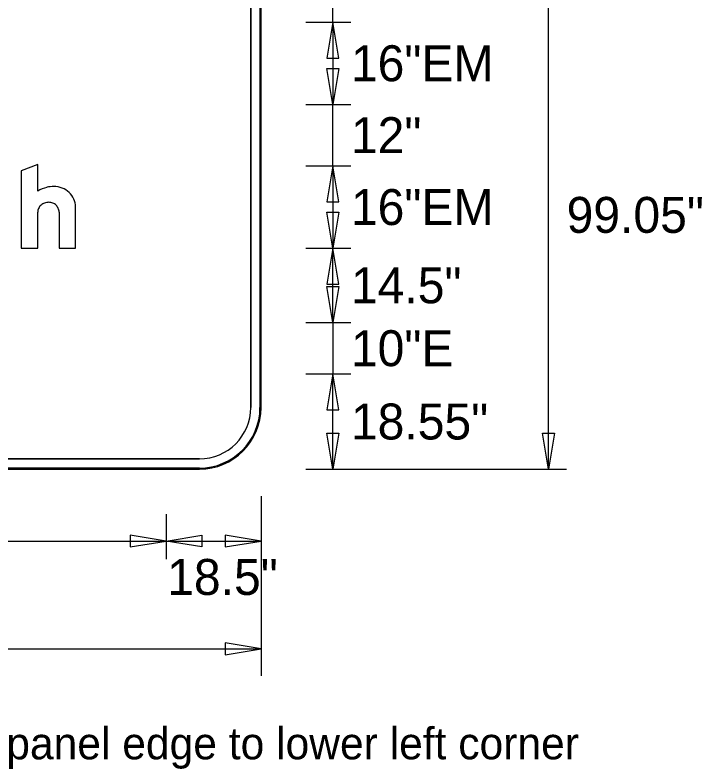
# Model space of a CAD drawing. Extents: x 2149961 to 2150220, y 145114 to 145240.
# Drawn here: x 2150101.79 to 2150112.93, y 145141.43 to 145153.67 of the extents above; entities that cross this region are included whole.
import ezdxf

# ---------------------------------------------------------------- set-up
doc = ezdxf.new("R2010")
doc.units = 0
for name, color, linetype in [('GSBWFILL', 7, 'Continuous'), ('GSCOLORFILL', 7, 'Continuous'), ('GSDIMS', 7, 'Continuous'), ('GSOUTLINE', 7, 'Continuous'), ('Level 1', 7, 'Continuous')]:
    doc.layers.add(name, color=color, linetype=linetype)

msp = doc.modelspace()

# ---------------------------------------------------------------- linework, layer by layer
at = {"layer": 'GSBWFILL'}
for p, q in [((2150105.612, 145159.8), (2150105.612, 145147.3)), ((2150105.779, 145147.3), (2150105.779, 145159.8)), ((2150104.779, 145146.466), (2150091.28, 145146.466)), ((2150091.28, 145146.3), (2150104.779, 145146.3))]:
    msp.add_line(p, q, dxfattribs=at)
for points in [[(2150102.155, 145150.812), (2150102.155, 145151.244), (2150101.888, 145151.141), (2150101.888, 145149.887), (2150102.155, 145149.887), (2150102.155, 145150.472)], [(2150102.501, 145150.472), (2150102.501, 145149.887), (2150102.768, 145149.887), (2150102.768, 145150.56)]]:
    msp.add_lwpolyline(points, dxfattribs=at)
for centre, radius, start, end in [((2150102.413, 145150.407), 0.48, 103.4695, 122.4943), ((2150102.417, 145150.354), 0.533, 90, 102.6043), ((2150102.417, 145150.512), 0.375, 68.8636, 90), ((2150102.426, 145150.535), 0.35, 46.975, 68.8636), ((2150102.44, 145150.55), 0.33, 23.9317, 46.975), ((2150102.462, 145150.56), 0.306, 0, 23.9317), ((2150102.315, 145150.462), 0.162, 131.0076, 154.5283), ((2150102.329, 145150.446), 0.183, 109.8074, 131.0076), ((2150102.338, 145150.421), 0.21, 90, 109.8074), ((2150102.338, 145150.463), 0.168, 68.0808, 90), ((2150102.339, 145150.467), 0.164, 45.8298, 68.0808), ((2150102.342, 145150.47), 0.159, 23.0928, 45.8298), ((2150102.294, 145150.472), 0.139, 154.5283, 180), ((2150102.347, 145150.472), 0.155, 0, 23.0928), ((2150104.779, 145147.3), 1, 270, 0), ((2150104.779, 145147.3), 0.833, 270, 0)]:
    msp.add_arc(centre, radius, start, end, dxfattribs=at)
at = {"layer": 'GSCOLORFILL'}
for p, q in [((2150105.612, 145159.8), (2150105.612, 145147.3)), ((2150105.762, 145159.8), (2150105.762, 145147.3)), ((2150105.779, 145147.3), (2150105.779, 145159.8)), ((2150105.779, 145147.3), (2150105.779, 145159.8)), ((2150105.779, 145147.3), (2150105.779, 145159.8)), ((2150104.779, 145146.466), (2150091.28, 145146.466)), ((2150104.779, 145146.316), (2150091.279, 145146.316)), ((2150091.279, 145146.3), (2150104.779, 145146.3)), ((2150091.279, 145146.3), (2150104.779, 145146.3)), ((2150091.28, 145146.3), (2150104.779, 145146.3))]:
    msp.add_line(p, q, dxfattribs=at)
for points in [[(2150102.155, 145150.812), (2150102.155, 145151.244), (2150101.888, 145151.141), (2150101.888, 145149.887), (2150102.155, 145149.887), (2150102.155, 145150.472)], [(2150102.501, 145150.472), (2150102.501, 145149.887), (2150102.768, 145149.887), (2150102.768, 145150.56)]]:
    msp.add_lwpolyline(points, dxfattribs=at)
for centre, radius, start, end in [((2150102.413, 145150.407), 0.48, 103.4695, 122.4943), ((2150102.417, 145150.354), 0.533, 90, 102.6043), ((2150102.417, 145150.512), 0.375, 68.8636, 90), ((2150102.426, 145150.535), 0.35, 46.975, 68.8636), ((2150102.44, 145150.55), 0.33, 23.9317, 46.975), ((2150102.462, 145150.56), 0.306, 0, 23.9317), ((2150102.315, 145150.462), 0.162, 131.0076, 154.5283), ((2150102.329, 145150.446), 0.183, 109.8074, 131.0076), ((2150102.338, 145150.421), 0.21, 90, 109.8074), ((2150102.338, 145150.463), 0.168, 68.0808, 90), ((2150102.339, 145150.467), 0.164, 45.8298, 68.0808), ((2150102.342, 145150.47), 0.159, 23.0928, 45.8298), ((2150102.294, 145150.472), 0.139, 154.5283, 180), ((2150102.347, 145150.472), 0.155, 0, 23.0928), ((2150104.779, 145147.3), 1, 270, 0), ((2150104.779, 145147.3), 1, 270, 0), ((2150104.779, 145147.3), 0.833, 270, 0), ((2150104.779, 145147.3), 1, 270, 0), ((2150104.779, 145147.3), 0.983, 270, 0)]:
    msp.add_arc(centre, radius, start, end, dxfattribs=at)
at = {"layer": 'GSDIMS'}
for p, q in [((2150106.945, 145153.554), (2150106.945, 145154.554)), ((2150110.445, 145146.3), (2150110.445, 145154.554)), ((2150106.508, 145153.554), (2150107.237, 145153.554)), ((2150106.508, 145153.554), (2150107.237, 145153.554)), ((2150106.945, 145153.554), (2150106.945, 145152.221)), ((2150106.508, 145152.221), (2150107.237, 145152.221)), ((2150106.508, 145152.221), (2150107.237, 145152.221)), ((2150106.945, 145151.221), (2150106.945, 145152.221)), ((2150106.508, 145151.221), (2150107.237, 145151.221)), ((2150106.508, 145151.221), (2150107.237, 145151.221)), ((2150106.945, 145151.221), (2150106.945, 145149.887)), ((2150106.508, 145149.887), (2150107.237, 145149.887)), ((2150106.508, 145149.887), (2150107.237, 145149.887)), ((2150106.945, 145148.679), (2150106.945, 145149.887)), ((2150106.508, 145148.679), (2150107.237, 145148.679)), ((2150106.508, 145148.679), (2150107.237, 145148.679)), ((2150106.945, 145148.679), (2150106.945, 145147.846)), ((2150106.508, 145147.846), (2150107.237, 145147.846)), ((2150106.508, 145147.846), (2150107.237, 145147.846)), ((2150106.945, 145146.3), (2150106.945, 145147.846)), ((2150106.508, 145146.3), (2150107.237, 145146.3)), ((2150106.508, 145146.3), (2150110.008, 145146.3)), ((2150110.008, 145146.3), (2150110.737, 145146.3)), ((2150105.779, 145145.862), (2150105.779, 145142.946)), ((2150104.237, 145145.571), (2150104.237, 145144.841)), ((2150104.237, 145145.571), (2150104.237, 145144.841)), ((2150105.779, 145145.571), (2150105.779, 145144.841)), ((2150091.82, 145145.133), (2150104.237, 145145.133)), ((2150104.237, 145145.133), (2150105.779, 145145.133)), ((2150105.779, 145143.821), (2150105.779, 145143.091)), ((2150090.279, 145143.383), (2150105.779, 145143.383))]:
    msp.add_line(p, q, dxfattribs=at)
for points in [[(2150106.945, 145153.554), (2150106.848, 145152.971), (2150107.043, 145152.971)], [(2150106.945, 145152.221), (2150106.848, 145152.804), (2150107.043, 145152.804)], [(2150106.945, 145151.221), (2150106.848, 145150.637), (2150107.043, 145150.637)], [(2150106.945, 145149.887), (2150106.848, 145150.471), (2150107.043, 145150.471)], [(2150106.945, 145149.887), (2150106.848, 145149.304), (2150107.043, 145149.304)], [(2150106.945, 145148.679), (2150106.848, 145149.262), (2150107.043, 145149.262)], [(2150106.945, 145147.846), (2150106.848, 145147.262), (2150107.043, 145147.262)], [(2150106.945, 145146.3), (2150106.848, 145146.883), (2150107.043, 145146.883)], [(2150110.445, 145146.3), (2150110.348, 145146.883), (2150110.543, 145146.883)], [(2150104.237, 145145.133), (2150103.654, 145145.23), (2150103.654, 145145.036)], [(2150104.237, 145145.133), (2150104.82, 145145.23), (2150104.82, 145145.036)], [(2150105.779, 145145.133), (2150105.195, 145145.23), (2150105.195, 145145.036)], [(2150105.779, 145143.383), (2150105.195, 145143.48), (2150105.195, 145143.286)]]:
    msp.add_lwpolyline(points, close=True, dxfattribs=at)
at = {"layer": 'GSOUTLINE'}
for p, q in [((2150105.612, 145147.3), (2150105.612, 145159.8)), ((2150105.779, 145147.3), (2150105.779, 145159.8)), ((2150091.279, 145146.466), (2150104.779, 145146.466)), ((2150091.279, 145146.3), (2150104.779, 145146.3))]:
    msp.add_line(p, q, dxfattribs=at)
for points in [[(2150102.155, 145150.812), (2150102.155, 145151.244), (2150101.888, 145151.141), (2150101.888, 145149.887), (2150102.155, 145149.887), (2150102.155, 145150.472)], [(2150102.501, 145150.472), (2150102.501, 145149.887), (2150102.768, 145149.887), (2150102.768, 145150.56)]]:
    msp.add_lwpolyline(points, dxfattribs=at)
for centre, radius, start, end in [((2150102.413, 145150.407), 0.48, 103.4695, 122.4943), ((2150102.417, 145150.354), 0.533, 90, 102.6043), ((2150102.417, 145150.512), 0.375, 68.8636, 90), ((2150102.426, 145150.535), 0.35, 46.975, 68.8636), ((2150102.44, 145150.55), 0.33, 23.9317, 46.975), ((2150102.462, 145150.56), 0.306, 0, 23.9317), ((2150102.315, 145150.462), 0.162, 131.0076, 154.5283), ((2150102.329, 145150.446), 0.183, 109.8074, 131.0076), ((2150102.338, 145150.421), 0.21, 90, 109.8074), ((2150102.338, 145150.463), 0.168, 68.0808, 90), ((2150102.339, 145150.467), 0.164, 45.8298, 68.0808), ((2150102.342, 145150.47), 0.159, 23.0928, 45.8298), ((2150102.294, 145150.472), 0.139, 154.5283, 180), ((2150102.347, 145150.472), 0.155, 0, 23.0928), ((2150104.779, 145147.3), 1, 270, 0), ((2150104.779, 145147.3), 0.833, 270, 0)]:
    msp.add_arc(centre, radius, start, end, dxfattribs=at)

# ---------------------------------------------------------------- texts
at = {"layer": 'GSDIMS'}
for s, p in [('16"EM', (2150107.237, 145152.596)), ('12"', (2150107.237, 145151.429)), ('16"EM', (2150107.237, 145150.262)), ('99.05"', (2150110.737, 145150.135)), ('14.5"', (2150107.237, 145148.991)), ('10"E', (2150107.237, 145147.971)), ('18.55"', (2150107.237, 145146.781)), ('18.5"', (2150104.256, 145144.258))]:
    msp.add_text(s, height=0.5833, dxfattribs=at).set_placement(p)
at = {"layer": 'Level 1'}
msp.add_text('Letter locations are panel edge to lower left corner', height=0.51652, dxfattribs=at).set_placement((2150095.579, 145141.59))

doc.saveas('drawing.dxf')
